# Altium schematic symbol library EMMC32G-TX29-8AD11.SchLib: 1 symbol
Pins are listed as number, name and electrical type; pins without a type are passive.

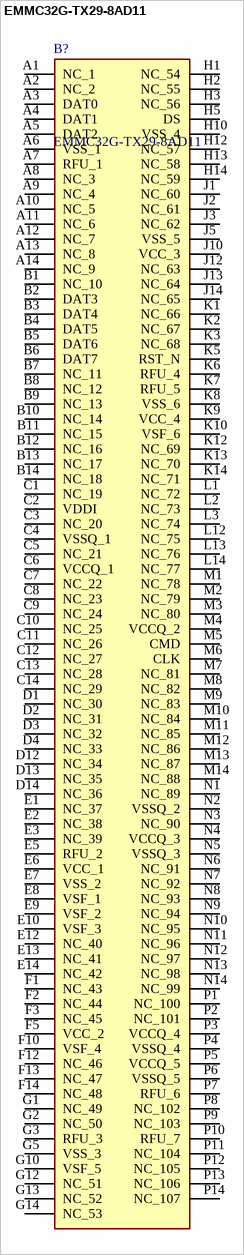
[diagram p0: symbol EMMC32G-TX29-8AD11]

## EMMC32G-TX29-8AD11
designator B?
eMMC 32GB eMMC 5.1 (HS400) 153B; Manufacturer_Name: Kingston Technology; Geometry.Height: 0.8mm
footprint BGA153C50P14X14_1150X1300X80
pins: A1 NC_1, A2 NC_2, A3 DAT0, A4 DAT1, A5 DAT2, A6 VSS_1, A7 RFU_1, A8 NC_3, A9 NC_4, A10 NC_5, A11 NC_6, A12 NC_7, A13 NC_8, A14 NC_9, B1 NC_10, B2 DAT3, B3 DAT4, B4 DAT5, B5 DAT6, B6 DAT7, B7 NC_11, B8 NC_12, B9 NC_13, B10 NC_14, B11 NC_15, B12 NC_16, B13 NC_17, B14 NC_18, C1 NC_19, C2 VDDI, C3 NC_20, C4 VSSQ_1, C5 NC_21, C6 VCCQ_1, C7 NC_22, C8 NC_23, C9 NC_24, C10 NC_25, C11 NC_26, C12 NC_27, C13 NC_28, C14 NC_29, D1 NC_30, D2 NC_31, D3 NC_32, D4 NC_33, D12 NC_34, D13 NC_35, D14 NC_36, E1 NC_37, E2 NC_38, E3 NC_39, E5 RFU_2, E6 VCC_1, E7 VSS_2, E8 VSF_1, E9 VSF_2, E10 VSF_3, E12 NC_40, E13 NC_41, E14 NC_42, F1 NC_43, F2 NC_44, F3 NC_45, F5 VCC_2, F10 VSF_4, F12 NC_46, F13 NC_47, F14 NC_48, G1 NC_49, G2 NC_50, G3 RFU_3, G5 VSS_3, G10 VSF_5, G12 NC_51, G13 NC_52, G14 NC_53, H1 NC_54, H2 NC_55, H3 NC_56, H5 DS, H10 VSS_4, H12 NC_57, H13 NC_58, H14 NC_59, J1 NC_60, J2 NC_61, J3 NC_62, J5 VSS_5, J10 VCC_3, J12 NC_63, J13 NC_64, J14 NC_65, K1 NC_66, K2 NC_67, K3 NC_68, K5 RST_N, K6 RFU_4, K7 RFU_5, K8 VSS_6, K9 VCC_4, K10 VSF_6, K12 NC_69, K13 NC_70, K14 NC_71, L1 NC_72, L2 NC_73, L3 NC_74, L12 NC_75, L13 NC_76, L14 NC_77, M1 NC_78, M2 NC_79, M3 NC_80, M4 VCCQ_2, M5 CMD, M6 CLK, M7 NC_81, M8 NC_82, M9 NC_83, M10 NC_84, M11 NC_85, M12 NC_86, M13 NC_87, M14 NC_88, N1 NC_89, N2 VSSQ_2, N3 NC_90, N4 VCCQ_3, N5 VSSQ_3, N6 NC_91, N7 NC_92, N8 NC_93, N9 NC_94, N10 NC_95, N11 NC_96, N12 NC_97, N13 NC_98, N14 NC_99, P1 NC_100, P2 NC_101, P3 VCCQ_4, P4 VSSQ_4, P5 VCCQ_5, P6 VSSQ_5, P7 RFU_6, P8 NC_102, P9 NC_103, P10 RFU_7, P11 NC_104, P12 NC_105, P13 NC_106, P14 NC_107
